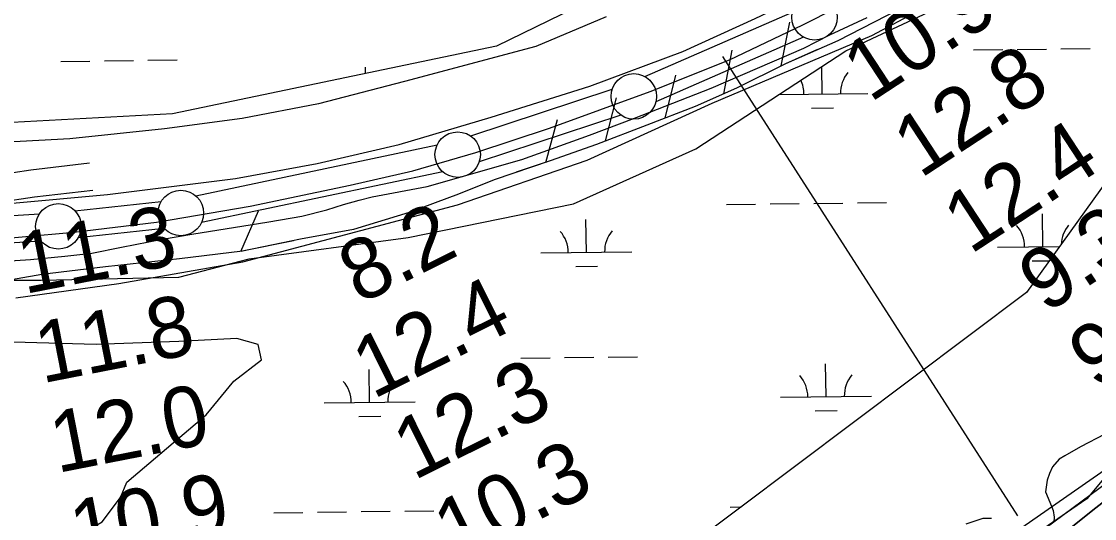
# Model space of a CAD drawing. Extents: x 3715084 to 3753216, y 488173 to 513963.
# Drawn here: x 3730139 to 3731319, y 500971 to 501517 of the extents above; entities that cross this region are included whole.
import ezdxf

# ---------------------------------------------------------------- set-up
doc = ezdxf.new("R2010")
doc.units = 0
for name, color, linetype in [('V-FLOD-BASE', 7, 'Continuous'), ('V-LEVE-TOET', 7, 'Continuous'), ('V-RIVR-EDGE', 7, 'Continuous'), ('V-RIVR-RANG', 7, 'Continuous'), ('V-ROAD-CNTR', 7, 'Continuous'), ('V-RRAP-FSHR', 7, 'Continuous'), ('V-SITE-VEGE', 7, 'Continuous'), ('V-SURV-LINE', 7, 'Continuous'), ('V-TOPO-DPTH', 7, 'Continuous'), ('V-TOPO-MINR', 7, 'Continuous'), ('V-TOPO-WATR', 7, 'Continuous'), ('V-WETL-SWMP', 7, 'Continuous')]:
    doc.layers.add(name, color=color, linetype=linetype)

msp = doc.modelspace()

# ---------------------------------------------------------------- linework, layer by layer
at = {"layer": 'V-FLOD-BASE'}
msp.add_lwpolyline([(3730083, 501275.3), (3730197, 501285.4), (3730287.6, 501296.6), (3730390.9, 501314), (3730500.5, 501337.1), (3730569.4, 501352.9), (3730639, 501373.1), (3730719.7, 501399.8), (3730830.6, 501440.2), (3730917.8, 501475.1), (3730998.5, 501513.4), (3731109.2, 501570), (3731216.8, 501630.2), (3731293.6, 501679.1), (3731346.7, 501713.7), (3731412.8, 501760.2), (3731484.4, 501811.6), (3731547.1, 501862.4), (3731607.1, 501917.2), (3731657.7, 501965.7)], dxfattribs=at)
at = {"layer": 'V-LEVE-TOET'}
for points in [[(3730125.3, 501317), (3730234, 501326.9), (3730374.7, 501344.5), (3730464.4, 501361.1), (3730554.6, 501382.1), (3730655.7, 501411.8), (3730764.1, 501446), (3730866.3, 501484.1), (3730945.8, 501520.4), (3731054, 501572.1), (3731169.1, 501640), (3731252.7, 501691.2), (3731313.4, 501729.4), (3731350.8, 501757.1), (3731389.1, 501783.2), (3731478.3, 501850.2), (3731556.7, 501917.3), (3731574.2, 501934.1), (3731603.4, 501964.1), (3731648.4, 502009.3)], [(3730070.4, 501250.5), (3730149.3, 501255.5), (3730187, 501259.2), (3730216.6, 501262.6), (3730249.4, 501269), (3730294.2, 501277.9), (3730326.7, 501283.2), (3730411.3, 501296.9), (3730447.6, 501303.1), (3730475.1, 501310.2), (3730493.2, 501315.9), (3730510.6, 501320.8), (3730524.8, 501324.3), (3730585.2, 501335.8), (3730689.3, 501365.3), (3730763.9, 501392.1), (3730813.2, 501410.9), (3730897.5, 501443.8), (3730999.3, 501488), (3731028.1, 501502.6), (3731069, 501521.7)]]:
    msp.add_lwpolyline(points, dxfattribs=at)
at = {"layer": 'V-RIVR-EDGE'}
msp.add_lwpolyline([(3731854, 501525.4), (3731837.1, 501503.2), (3731817.3, 501495.5), (3731803.5, 501502.1), (3731791.5, 501502.1), (3731772.2, 501489.6), (3731731.9, 501432.6), (3731688.5, 501378.7), (3731649.9, 501321.2), (3731608.4, 501269.1), (3731589.2, 501267.9), (3731571.7, 501257.7), (3731562.7, 501242.7), (3731552.4, 501217), (3731544, 501197.8), (3731528.9, 501167.8), (3731441.7, 501099.6), (3731375.5, 501045.7), (3731344.9, 501035.6), (3731329.2, 501014.6), (3731310.5, 500992.4), (3731251.6, 500951.8)], dxfattribs=at)
at = {"layer": 'V-RIVR-RANG'}
msp.add_line((3730910, 501478.6), (3731234.2, 500973.8), dxfattribs=at)
at = {"layer": 'V-ROAD-CNTR'}
for points in [[(3728474.7, 501538.3), (3728912.7, 501468.7), (3729598.4, 501361.6), (3729765.1, 501348.3), (3729904.9, 501338.3), (3730027.7, 501341.6), (3730110.5, 501348.3), (3730149.5, 501354.1), (3730214.2, 501361.6)], [(3728470, 501508.6), (3728908, 501439), (3729594.9, 501331.8), (3729762.9, 501318.4), (3729904.3, 501308.3), (3730029.3, 501311.7), (3730113.9, 501318.4), (3730153.5, 501324.3), (3730217.7, 501331.8)]]:
    msp.add_lwpolyline(points, dxfattribs=at)
at = {"layer": 'V-RRAP-FSHR'}
for p, q in [((3730974.4, 501468.5), (3730983.9, 501516.4)), ((3730911.5, 501437.8), (3730920.7, 501485.7)), ((3730846.9, 501410.8), (3730858.6, 501458.3)), ((3730781.5, 501385.9), (3730793.5, 501433.2)), ((3730715.6, 501362.3), (3730728.6, 501409.3)), ((3730380.6, 501264.3), (3730400, 501309.1))]:
    msp.add_line(p, q, dxfattribs=at)
for points in [[(3731103.2, 501530), (3731036.8, 501496), (3730979.4, 501470.7), (3730925.3, 501444), (3730879.9, 501423.6), (3730826.9, 501403.1), (3730771.5, 501382.1), (3730720.7, 501364.1), (3730658.8, 501343.1), (3730619.8, 501327.4), (3730565.5, 501307.2), (3730504.4, 501288.3), (3730445.9, 501277.7), (3730382.3, 501264.6), (3730312.9, 501256.3), (3730231.7, 501247.4), (3730161.5, 501239.1), (3730106.9, 501229.3)], [(3731014.6, 501486.3), (3730979.4, 501470.7), (3730925.3, 501444), (3730879.9, 501423.6), (3730826.9, 501403.1), (3730771.5, 501382.1), (3730720.7, 501364.1), (3730683.2, 501351.4)], [(3730438.2, 501276.1), (3730383.7, 501264.9)]]:
    msp.add_lwpolyline(points, dxfattribs=at)
at = {"layer": 'V-SITE-VEGE'}
for points in [[(3730133.1, 501213.5), (3730246.2, 501229.1), (3730382.5, 501252.9), (3730618.5, 501315.6), (3730761.4, 501364.6), (3730898.6, 501427.4), (3731074.2, 501501.7), (3731179.1, 501557.7)], [(3730782, 501522.4), (3730704.7, 501489.8), (3730560.5, 501451), (3730465.8, 501426.8), (3730382.1, 501410.5)], [(3730382.1, 501410.5), (3730296.4, 501399), (3730192.6, 501388.2), (3730069.4, 501381.6)], [(3731330.2, 501063.6), (3731303.7, 501049.7), (3731286.3, 501039.7), (3731280.2, 501035.8), (3731272.8, 501027.7), (3731269.5, 501020.2), (3731266.9, 501012.9), (3731265, 501000), (3731271.8, 500984.3), (3731273.4, 500979.6), (3731274.8, 500972.3), (3731274.4, 500966.6)], [(3731205.8, 500970.6), (3731196.3, 500970.8), (3731177.4, 500964.4)]]:
    msp.add_lwpolyline(points, dxfattribs=at)
at = {"layer": 'V-SURV-LINE'}
for points in [[(3730824.8, 501456.5), (3730986.9, 501527.5)], [(3730998.9, 501500), (3730836.8, 501429)], [(3730633.2, 501391.3), (3730788.8, 501442.7)], [(3730798.2, 501414.3), (3730642.5, 501362.8)], [(3730330.9, 501325.4), (3730596.2, 501381.4)], [(3730602.4, 501352), (3730337.2, 501296.1)], [(3730198.1, 501309), (3730293, 501319.4)], [(3730006.5, 501296.1), (3730159, 501305.7)], [(3730296.3, 501289.5), (3730201.4, 501279.2)], [(3730160.9, 501275.7), (3730008.4, 501266.1)]]:
    msp.add_lwpolyline(points, dxfattribs=at)
for centre in [(3731011.2, 501521.8), (3730812.5, 501434.8), (3730618.9, 501370.8), (3730314.5, 501306.6), (3730179.9, 501291.9)]:
    msp.add_circle(centre, 25, dxfattribs=at)
at = {"layer": 'V-TOPO-DPTH'}
for points in [[(3731426.1, 501090.6), (3731147.6, 500896.6), (3731099.8, 500863.1), (3731052.2, 500829.3), (3731004.9, 500795.2), (3730957.8, 500760.8), (3730904.8, 500721.9), (3730884, 500707.2), (3730862.9, 500693.1), (3730841.3, 500679.7), (3730819.4, 500666.8), (3730745.3, 500625.2), (3730691.4, 500596.5), (3730636.8, 500569.5), (3730581, 500544.9), (3730524.4, 500521.9), (3730419.4, 500482.1), (3730414.7, 500480.4), (3730410, 500478.8), (3730405.2, 500477.4), (3730400.4, 500476), (3730099, 500399.8)], [(3731268.7, 500941.2), (3731317.3, 500979.8), (3731421.6, 501061.2)], [(3731268.7, 500941.2), (3731317.3, 500979.8), (3731421.6, 501061.2)]]:
    msp.add_lwpolyline(points, dxfattribs=at)
at = {"layer": 'V-TOPO-MINR'}
for points in [[(3731424.1, 501077.9), (3731264.5, 500959.3)], [(3731421.6, 501061.2), (3731317.3, 500979.8), (3731268.7, 500941.2)]]:
    msp.add_lwpolyline(points, dxfattribs=at)
at = {"layer": 'V-TOPO-WATR'}
msp.add_lwpolyline([(3731426.1, 501090.6), (3731147.6, 500896.6), (3731099.8, 500863.1), (3731052.2, 500829.3), (3731004.9, 500795.2), (3730957.8, 500760.8), (3730904.8, 500721.9), (3730884, 500707.2), (3730862.9, 500693.1), (3730841.3, 500679.7), (3730819.4, 500666.8), (3730745.3, 500625.2), (3730691.4, 500596.5), (3730636.8, 500569.5), (3730581, 500544.9), (3730524.4, 500521.9), (3730419.4, 500482.1), (3730414.7, 500480.4), (3730410, 500478.8), (3730405.2, 500477.4), (3730400.4, 500476), (3730099, 500399.8)], dxfattribs=at)
at = {"layer": 'V-WETL-SWMP'}
for p, q in [((3731234.1, 501486.5), (3731266.1, 501486.9)), ((3731282.1, 501487.1), (3731314.1, 501487.5)), ((3730278.4, 501474.5), (3730310.4, 501474.9)), ((3731186.1, 501485.9), (3731218.1, 501486.3)), ((3730182.4, 501473.3), (3730214.4, 501473.7)), ((3730230.4, 501473.9), (3730262.4, 501474.3)), ((3730517.4, 501459.8), (3730517.4, 501467.1)), ((3731019.7, 501437.4), (3731019.3, 501467.8)), ((3730971.9, 501436.8), (3731069.7, 501438)), ((3731007.9, 501421.8), (3731031.9, 501422.1)), ((3730914.3, 501316), (3730946.3, 501316.4)), ((3730962.3, 501316.6), (3730994.3, 501317)), ((3731010.3, 501317.2), (3731042.3, 501317.6)), ((3731058.3, 501317.8), (3731090.3, 501318.2)), ((3730760.4, 501263.3), (3730759.9, 501299.3)), ((3731262.3, 501269.6), (3731261.8, 501305.6)), ((3730710.4, 501262.7), (3730810.4, 501263.9)), ((3731212.3, 501269), (3731280.6, 501269.8)), ((3731250.5, 501254), (3731269.4, 501254.2)), ((3730748.6, 501247.7), (3730772.6, 501248)), ((3730688.4, 501147), (3730720.4, 501147.4)), ((3730736.4, 501147.6), (3730768.4, 501148)), ((3730784.4, 501148.2), (3730816.4, 501148.6)), ((3730522, 501098.5), (3730521.5, 501134.5)), ((3731023.8, 501104.7), (3731023.4, 501140.7)), ((3730472, 501097.8), (3730572, 501099.1)), ((3730973.8, 501104.1), (3731073.8, 501105.4)), ((3731012, 501089.1), (3731036, 501089.4)), ((3730510.2, 501082.9), (3730534.2, 501083.2)), ((3730560.6, 500978.9), (3730592.6, 500979.3)), ((3730918.5, 500983.3), (3730930.8, 500983.5)), ((3730416.6, 500977.1), (3730448.6, 500977.5)), ((3730464.6, 500977.7), (3730496.6, 500978.1)), ((3730512.6, 500978.3), (3730544.6, 500978.7))]:
    msp.add_line(p, q, dxfattribs=at)
for points in [[(3732459.3, 504480.8), (3732424.6, 503990.6), (3732325.6, 503411.2), (3732300.8, 503223), (3732251.3, 503079.4), (3732157.2, 502856.6), (3732073, 502688.2), (3732038.4, 502584.2), (3731914.6, 502376.3), (3731716.5, 502133.6), (3731459, 501930.6), (3731201.5, 501747.4), (3730904.4, 501608.7), (3730661.7, 501489.9), (3730305.2, 501415.6), (3729938.8, 501395.8)], [(3730036.4, 501232.6), (3730160.8, 501232.6), (3730312.2, 501236), (3730389.6, 501256.2), (3730564.5, 501279.7), (3730746.2, 501316.7), (3730880.8, 501377.3), (3731045.6, 501485), (3731217.2, 501565.7)], [(3731486.4, 501552.2), (3731439.3, 501501.8), (3731419.1, 501464.8), (3731365.2, 501387.4), (3731244.1, 501219.2), (3730864, 500933.2), (3730557.8, 500778.5), (3730517.4, 500754.9), (3730467, 500728), (3730406.4, 500711.2), (3730312.2, 500687.6), (3730224.8, 500657.3), (3730100.3, 500630.4)], [(3730399.7, 501162), (3730376.1, 501168.7), (3730312.2, 501165.4), (3730221.4, 501162), (3730103.6, 501165.4)], [(3730130.6, 500923.1), (3730181, 500939.9), (3730228.1, 500966.9), (3730248.3, 500993.8), (3730255, 501010.6), (3730342.5, 501084.6), (3730372.8, 501121.6), (3730403.1, 501145.2), (3730399.7, 501162)]]:
    msp.add_lwpolyline(points, dxfattribs=at)
for centre, start, end in [((3730462.6, 501430.9), 40.8313, 41.4878), ((3730964.4, 501437.2), 359.9442, 26.0023), ((3731074.9, 501438.5), 139.9442, 181.4878), ((3730705.2, 501263.1), 359.9442, 41.4878), ((3730815.6, 501264.5), 139.9442, 181.4878), ((3731207, 501269.4), 359.9442, 41.4878), ((3731317.5, 501270.7), 139.9442, 177.698), ((3730466.7, 501098.2), 359.9442, 41.4878), ((3730577.2, 501099.6), 139.9442, 181.4878), ((3730968.6, 501104.5), 359.9442, 41.4878), ((3731079.1, 501105.9), 139.9442, 181.4878)]:
    msp.add_arc(centre, 35.2, start, end, dxfattribs=at)

# ---------------------------------------------------------------- texts
at = {"layer": 'V-RIVR-RANG'}
for s, rotation, p in [('10.9', 33.2483, (3731072.3, 501427.3)), ('12.8', 33.2483, (3731127.5, 501343.9)), ('12.4', 33.2483, (3731182.5, 501260.4)), ('11.3', 11.0883, (3730142.3, 501217.3)), ('8.2', 26.4483, (3730510.8, 501205.7)), ('9.3', 33.2483, (3731265.4, 501195.2)), ('12.4', 26.4483, (3730525.8, 501101.5)), ('9.4', 33.2483, (3731320.4, 501111.7)), ('11.8', 11.0883, (3730161.8, 501119.2)), ('12.3', 26.4483, (3730570.6, 501012.1)), ('12.0', 11.0883, (3730178.4, 501020.6)), ('10.3', 26.4483, (3730615.3, 500922.7)), ('10.9', 11.0883, (3730200.5, 500923))]:
    msp.add_text(s, height=67, rotation=rotation, dxfattribs=at).set_placement(p)

doc.saveas('drawing.dxf')
